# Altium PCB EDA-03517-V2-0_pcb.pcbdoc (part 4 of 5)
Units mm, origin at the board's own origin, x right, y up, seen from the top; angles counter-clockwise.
Board outline 220 x 264 mm, 8 copper layers (Top Layer, L2, L3, L4, L5, L6, L7, Bottom Layer), stack 2.18 mm thick; 439 components, 290 nets, 1011 pads, 273 vias.
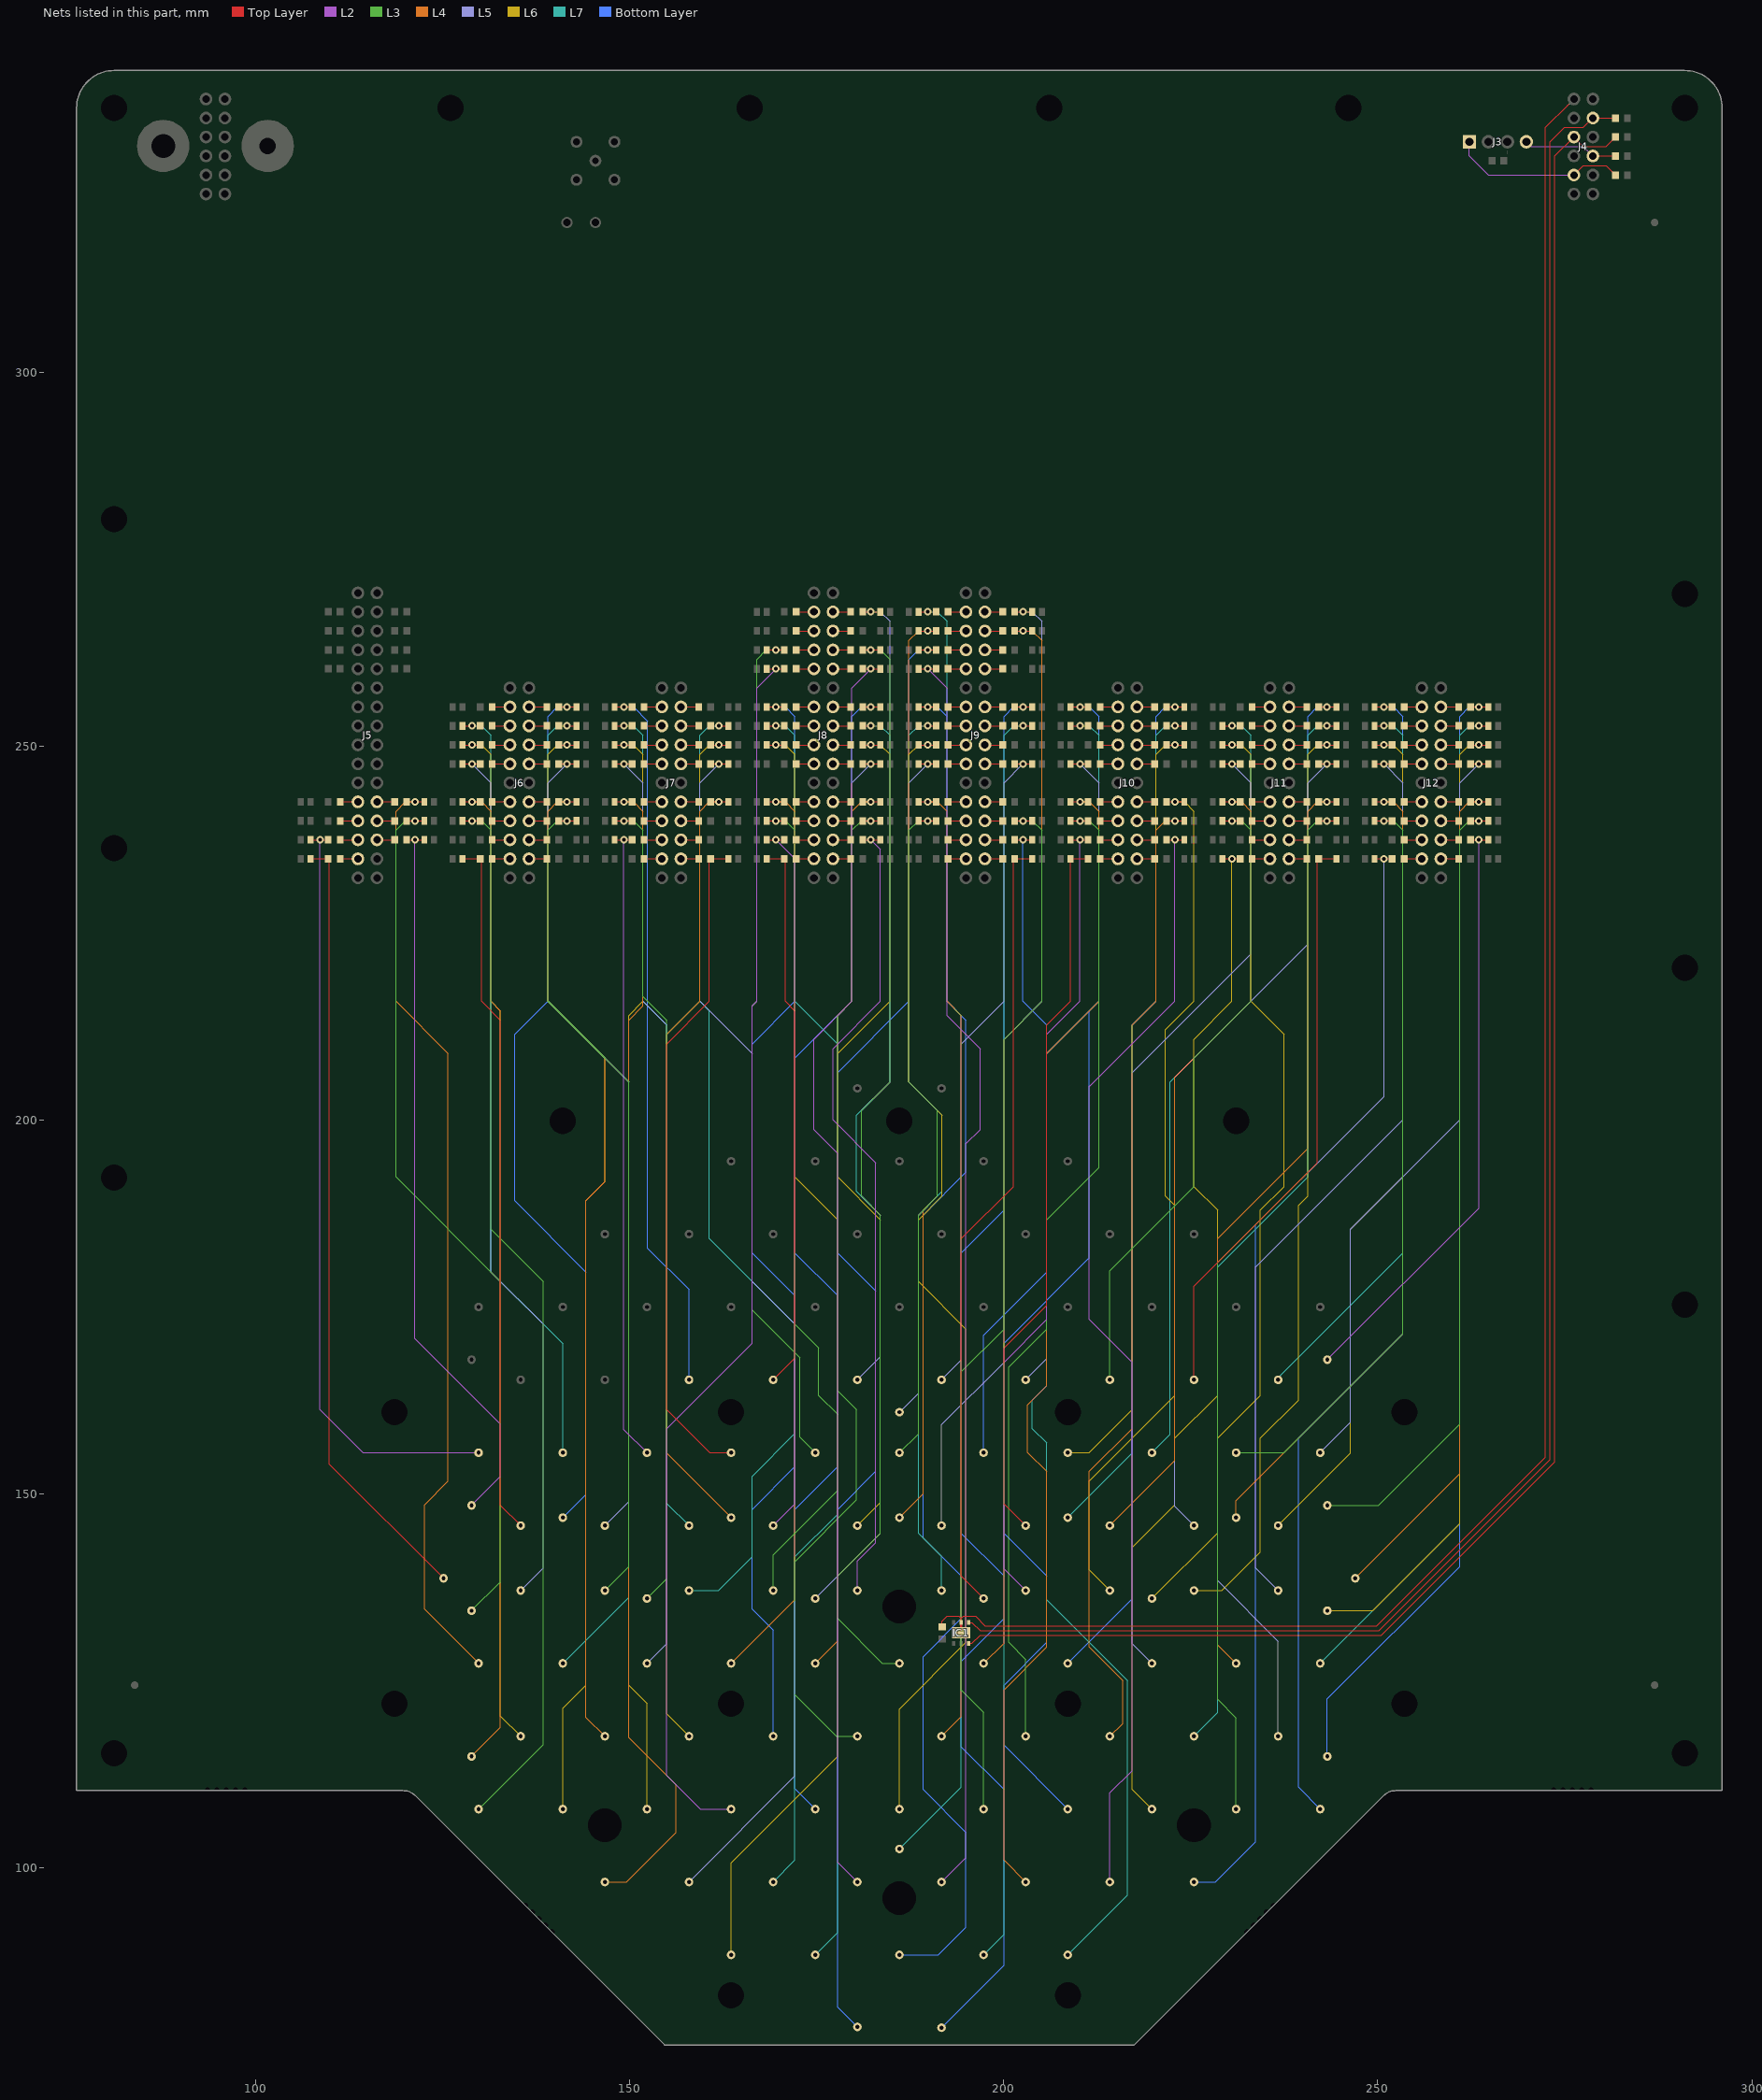
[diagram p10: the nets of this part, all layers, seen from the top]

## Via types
v1: diameter 1, hole 0.5, Top Layer to Bottom Layer, tented both sides, 273 vias

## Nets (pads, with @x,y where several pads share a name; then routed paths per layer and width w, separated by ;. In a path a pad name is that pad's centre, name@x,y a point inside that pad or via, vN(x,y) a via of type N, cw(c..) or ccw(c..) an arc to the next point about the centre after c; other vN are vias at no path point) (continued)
NetPP30_1: PP30.1 RB19.1 RS19.1 | length 96.7
  Top Layer w0.152: RB19.1@147.97,255.27 v1(149.225,255.27) RS19.1@150.33,255.27
  Bottom Layer w0.152: v1(149.225,255.27) 150.495,255.27 152.4,253.365 152.4,182.88 157.925,177.355 PP30.1@157.925,165.283
NetPP31_1: PP31.1 RB124.1 RS124.1 | length 73.8
  Top Layer w0.152: RB124.1@168.29,234.95 RS124.1@170.65,234.95 170.815,234.785 170.815,215.9 172.085,214.63 172.085,168.191 PP31.1@169.177,165.283
NetPP32_1: PP32.1 RB2.1 RS2.1 | length 110.8
  Top Layer w0.152: RS2.1@181.14,267.97 RB2.1@183.5,267.97
  L5 w0.152: PP32.1@180.429,165.283 183.515,168.369 183.515,187.325 180.975,189.865 180.975,201.295 184.785,205.105 184.785,266.7 183.515,267.97 v1(182.245,267.97)
NetPP33_1: PP33.1 RB65.1 RS65.1 | length 89.2
  Top Layer w0.152: RS65.1@201.46,247.65 RB65.1@203.82,247.65
  L5 w0.152: PP33.1@191.681,165.283 194.31,167.912 194.31,210.185 200.025,215.9 200.025,245.11 v1(202.565,247.65)
NetPP34_1: PP34.1 RB67.1 RS67.1 | length 89.8
  Top Layer w0.152: RB67.1@208.93,247.65 v1(210.185,247.65) RS67.1@211.29,247.65
  L5 w0.152: PP34.1@202.933,165.283 205.74,168.09 205.74,208.915 212.725,215.9 212.725,245.11 v1(210.185,247.65)
NetPP35_1: PP35.1 RB101.1 RS101.1 | length 86.7
  Top Layer w0.152: RB101.1@229.25,240.03 v1(230.505,240.03) RS101.1@231.61,240.03
  L3 w0.152: PP35.1@214.185,165.283 214.185,179.895 225.425,191.135 225.425,208.28 233.045,215.9 233.045,238.76 231.775,240.03 v1(230.505,240.03)
NetPP36_1: PP36.1 RB133.1 RS133.1 | length 78.9
  Top Layer w0.152: PP36.1@225.437,165.283 225.437,177.812 241.935,194.31 241.935,234.785 RS133.1@242.1,234.95 RB133.1@244.475,234.95
NetPP37_1: PP37.1 RB43.1 RS43.1 | length 98.5
  Top Layer w0.152: RB43.1@249.57,252.73 v1(250.825,252.73) RS43.1@251.93,252.73
  L7 w0.152: PP37.1@236.689,165.283 236.689,165.569 253.365,182.245 253.365,222.885 253.365,251.46 252.095,252.73 v1(250.825,252.73)
NetPP38_1: PP38.1 RB120.1 RS120.1 | length 80.3
  Top Layer w0.152: RS120.1@262.42,237.49 v1(263.525,237.49) RB120.1@264.78,237.49
  L2 w0.152: PP38.1@243.258,167.986 263.525,188.253 v1(263.525,237.49)
NetPP39_1: PP39.1 RB66.1 RS66.1 | length 93.8
  Top Layer w0.152: RB66.1@188.61,247.65 v1(189.865,247.65) RS66.1@190.97,247.65
  L5 w0.152: PP39.1@186.055,160.96 188.595,163.5 188.595,187.325 191.135,189.865 191.135,201.295 187.325,205.105 187.325,245.11 v1(189.865,247.65)
NetPP40_1: PP40.1 RB105.1 RS105.1 | length 102.2
  Top Layer w0.152: RB105.1@107.33,237.49 v1(108.585,237.49) RS105.1@109.69,237.49
  L2 w0.152: v1(108.585,237.49) 108.585,161.29 114.337,155.538 PP40.1@129.795,155.538
NetPP41_1: PP41.1 RB31.1 RS31.1 | length 105.3
  Top Layer w0.152: RB31.1@127.65,252.73 v1(128.905,252.73) RS31.1@130.01,252.73
  L7 w0.152: v1(128.905,252.73) 130.175,252.73 131.445,251.46 131.445,179.705 141.047,170.103 PP41.1@141.047,155.538
NetPP42_1: PP42.1 RB108.1 RS108.1 | length 85.6
  Top Layer w0.152: RB108.1@147.97,237.49 RS108.1@150.33,237.49
  L2 w0.152: v1(149.225,237.49) 149.225,158.612 PP42.1@152.299,155.538
NetPP43_1: PP43.1 RB128.1 RS128.1 | length 89.4
  Top Layer w0.152: RB128.1@163.18,234.95 RS128.1@160.82,234.95 160.655,234.785 160.655,215.9 154.94,210.185 154.94,161.29 160.692,155.538 PP43.1@163.551,155.538
NetPP44_1: PP44.1 RB9.1 RS9.1 | length 115.3
  Top Layer w0.152: RB9.1@168.29,262.89 v1(169.545,262.89) RS9.1@170.65,262.89
  L3 w0.152: v1(169.545,262.89) 168.275,262.89 167.005,261.62 167.005,215.9 166.37,215.265 166.37,174.625 172.72,168.275 172.72,157.621 PP44.1@174.803,155.538
NetPP45_1: PP45.1 RB98.1 RS98.1 | length 92.3
  Top Layer w0.152: RB98.1@188.61,240.03 v1(189.865,240.03) RS98.1@190.97,240.03
  L3 w0.152: PP45.1@186.055,155.538 188.595,158.078 188.595,187.325 191.135,189.865 191.135,201.295 187.325,205.105 187.325,238.76 188.595,240.03 v1(189.865,240.03)
NetPP46_1: PP46.1 RB111.1 RS111.1 | length 89.1
  Top Layer w0.152: RS111.1@201.46,237.49 v1(202.565,237.49) RB111.1@203.82,237.49
  Bottom Layer w0.152: PP46.1@197.307,155.538 197.307,171.272 205.74,179.705 205.74,212.725 202.565,215.9 v1(202.565,237.49)
NetPP47_1: PP47.1 RB54.1 RS54.1 | length 105.4
  Top Layer w0.152: RS54.1@221.78,250.19 v1(222.885,250.19) RB54.1@224.14,250.19
  L6 w0.152: PP47.1@208.559,155.538 211.418,155.538 217.17,161.29 217.17,212.725 220.345,215.9 220.345,248.92 221.615,250.19 v1(222.885,250.19)
NetPP48_1: PP48.1 RB41.1 RS41.1 | length 106.8
  Top Layer w0.152: RB41.1@229.25,252.73 v1(230.505,252.73) RS41.1@231.61,252.73
  L7 w0.152: PP48.1@219.811,155.538 222.25,157.977 222.25,205.105 233.045,215.9 233.045,251.46 231.775,252.73 v1(230.505,252.73)
NetPP49_1: PP49.1 RB103.1 RS103.1 | length 101.6
  Top Layer w0.152: RB103.1@249.57,240.03 v1(250.825,240.03) RS103.1@251.93,240.03
  L3 w0.152: PP49.1@231.063,155.538 237.453,155.538 253.365,171.45 253.365,238.76 252.095,240.03 v1(250.825,240.03)
NetPP50_1: PP50.1 RB72.1 RS72.1 | length 103.3
  Top Layer w0.152: RS72.1@262.42,247.65 v1(263.525,247.65) RB72.1@264.78,247.65
  L5 w0.152: PP50.1@242.315,155.538 246.38,159.603 246.38,185.42 260.985,200.025 260.985,245.11 v1(263.525,247.65)
NetPP51_1: PP51.1 RB106.1 RS106.1 | length 97.7
  Top Layer w0.152: RS106.1@120.18,237.49 v1(121.285,237.49) RB106.1@122.54,237.49
  L2 w0.152: v1(121.285,237.49) 121.285,170.815 132.715,159.385 132.715,152.36 PP51.1@128.852,148.497
NetPP52_1: PP52.1 RB127.1 RS127.1 | length 93.8
  Top Layer w0.152: RB127.1@127.65,234.95 RS127.1@130.01,234.95 130.175,234.785 130.175,215.9 132.715,213.36 132.715,148.5 PP52.1@135.421,145.794
NetPP53_1: PP53.1 RB60.1 RS60.1 | length 111.1
  Top Layer w0.152: RS60.1@140.5,247.65 v1(141.605,247.65) RB60.1@142.86,247.65
  L5 w0.152: v1(141.605,247.65) 139.065,245.11 139.065,215.9 149.86,205.105 149.86,148.981 PP53.1@146.673,145.794
NetPP54_1: PP54.1 RB33.1 RS33.1 | length 113.6
  Top Layer w0.152: RB33.1@147.97,252.73 v1(149.225,252.73) RS33.1@150.33,252.73
  L7 w0.152: v1(149.225,252.73) 150.495,252.73 151.765,251.46 151.765,215.9 154.94,212.725 154.94,148.779 PP54.1@157.925,145.794
NetPP55_1: PP55.1 RB109.1 RS109.1 | length 96.3
  Top Layer w0.152: RB109.1@168.29,237.49 v1(169.545,237.49) RS109.1@170.65,237.49
  L2 w0.152: PP55.1@169.177,145.794 172.085,148.702 172.085,234.95 v1(169.545,237.49)
NetPP56_1: PP56.1 RB50.1 RS50.1 | length 115.1
  Top Layer w0.152: RS50.1@181.14,250.19 RB50.1@183.5,250.19
  L6 w0.152: PP56.1@180.429,145.794 183.515,148.88 183.515,186.69 177.8,192.405 177.8,208.915 184.785,215.9 184.785,248.92 183.515,250.19 v1(182.245,250.19)
NetPP57_1: PP57.1 RB3.1 RS4.1 | length 131.9
  Top Layer w0.152: RS4.1@201.46,267.97 RB3.1@203.82,267.97
  L5 w0.152: PP57.1@191.681,145.794 191.681,159.296 200.025,167.64 200.025,210.82 205.105,215.9 205.105,225.425 205.105,266.7 203.835,267.97 v1(202.565,267.97)
NetPP58_1: PP58.1 RB130.1 RS130.1 | length 96.4
  Top Layer w0.152: PP58.1@202.933,145.794 200.025,148.702 200.025,169.545 205.74,175.26 205.74,212.725 208.915,215.9 208.915,234.935 RB130.1@208.93,234.95 RS130.1@211.29,234.95
NetPP59_1: PP59.1 RB85.1 RS85.1 | length 108.7
  Top Layer w0.152: RB85.1@229.25,242.57 RS85.1@231.61,242.57
  L4 w0.152: PP59.1@214.185,145.794 222.885,154.494 222.885,205.74 233.045,215.9 233.045,241.3 231.775,242.57 v1(230.505,242.57)
NetPP60_1: PP60.1 RB70.1 RS70.1 | length 113.7
  Top Layer w0.152: RS70.1@242.1,247.65 v1(243.205,247.65) RB70.1@244.46,247.65
  L5 w0.152: PP60.1@225.437,145.794 222.885,148.346 222.885,205.74 240.665,223.52 240.665,245.11 v1(243.205,247.65)
NetPP61_1: PP61.1 RB57.1 RS57.1 | length 115.5
  Top Layer w0.152: RB57.1@249.57,250.19 v1(250.825,250.19) RS57.1@251.93,250.19
  L6 w0.152: PP61.1@236.689,145.794 246.38,155.485 246.38,185.42 253.365,192.405 253.365,248.92 252.095,250.19 v1(250.825,250.19)
NetPP62_1: PP62.1 RB104.1 RS104.1 | length 107
  Top Layer w0.152: RS104.1@262.42,240.03 v1(263.525,240.03) RB104.1@264.78,240.03
  L3 w0.152: PP62.1@243.258,148.497 250.097,148.497 260.985,159.385 260.985,238.76 262.255,240.03 v1(263.525,240.03)
NetPP63_1: PP63.1 RB121.1 RS121.1 | length 104.9
  Top Layer w0.152: RB121.1@107.33,234.95 RS121.1@109.69,234.95 109.855,234.785 109.855,154.01 PP63.1@125.112,138.753
NetPP64_1: PP64.1 RB18.1 RS18.1 | length 119.6
  Top Layer w0.152: RS18.1@140.5,255.27 RB18.1@142.86,255.27
  Bottom Layer w0.152: PP64.1@141.047,146.864 144.145,149.962 144.145,179.705 134.62,189.23 134.62,211.455 139.065,215.9 139.065,254 140.335,255.27 v1(141.605,255.27)
NetPP65_1: PP65.1 RB92.1 RS92.1 | length 110.5
  Top Layer w0.152: RB92.1@147.97,240.03 RS92.1@150.33,240.03
  L3 w0.152: v1(149.225,240.03) 150.495,240.03 151.765,238.76 151.765,216.535 154.94,213.36 154.94,138.69 PP65.1@152.299,136.049
NetPP66_1: PP66.1 RB81.1 RS81.1 | length 105.3
  Top Layer w0.152: RS81.1@160.82,242.57 RB81.1@163.18,242.57
  L4 w0.152: v1(161.925,242.57) 160.655,242.57 159.385,241.3 159.385,221.297 159.385,215.9 154.94,211.455 154.94,155.475 PP66.1@163.551,146.864
NetPP67_1: PP67.1 RB64.1 RS64.1 | length 117
  Top Layer w0.152: RS64.1@181.14,247.65 RB64.1@183.5,247.65
  L5 w0.152: PP67.1@174.803,136.049 177.8,139.046 177.8,213.995 179.705,215.9 179.705,245.11 v1(182.245,247.65)
NetPP68_1: PP68.1 RB8.1 RS7.1 | length 126.4
  Top Layer w0.152: RB8.1@188.61,265.43 v1(189.865,265.43) RS7.1@190.97,265.43
  L4 w0.152: PP68.1@186.055,146.864 189.23,150.039 189.23,187.96 191.135,189.865 191.135,201.295 187.325,205.105 187.325,264.16 188.595,265.43 v1(189.865,265.43)
NetPP69_1: PP69.1 RB126.1 RS126.1 | length 105.5
  Top Layer w0.152: PP69.1@197.307,136.049 194.31,139.046 194.31,184.15 201.295,191.135 201.295,234.785 RS126.1@201.46,234.95 RB126.1@203.82,234.95
NetPP70_1: PP70.1 RB40.1 RS40.1 | length 114.9
  Top Layer w0.152: RS40.1@221.78,252.73 RB40.1@224.14,252.73
  L7 w0.152: PP70.1@208.559,146.864 217.17,155.475 217.17,212.725 220.345,215.9 220.345,251.46 221.615,252.73 v1(222.885,252.73)
NetPP71_1: PP71.1 RB55.1 RS55.1 | length 127.5
  Top Layer w0.152: RB55.1@229.25,250.19 v1(230.505,250.19) RS55.1@231.61,250.19
  L6 w0.152: PP71.1@219.811,136.049 228.6,144.838 228.6,157.48 234.315,163.195 234.315,187.96 237.49,191.135 237.49,211.455 233.045,215.9 233.045,248.92 231.775,250.19 v1(230.505,250.19)
NetPP72_1: PP72.1 RB87.1 RS87.1 | length 109.1
  Top Layer w0.152: RB87.1@249.57,242.57 v1(250.825,242.57) RS87.1@251.93,242.57
  L4 w0.152: PP72.1@231.063,146.864 231.063,149.148 253.365,171.45 253.365,241.3 252.095,242.57 v1(250.825,242.57)
NetPP73_1: PP73.1 RB88.1 RS88.1 | length 113.8
  Top Layer w0.152: RS88.1@262.42,242.57 v1(263.525,242.57) RB88.1@264.78,242.57
  L4 w0.152: PP73.1@246.998,138.753 260.985,152.74 260.985,241.3 262.255,242.57 v1(263.525,242.57)
NetPP74_1: PP74.1 RB90.1 RS90.1 | length 117.2
  Top Layer w0.152: RS90.1@120.18,240.03 v1(121.285,240.03) RB90.1@122.54,240.03
  L3 w0.152: v1(121.285,240.03) 120.015,240.03 118.745,238.76 118.745,192.405 132.715,178.435 132.715,138.279 PP74.1@128.852,134.415
NetPP75_1: PP75.1 RB59.1 RS59.1 | length 118.1
  Top Layer w0.152: RB59.1@127.65,247.65 v1(128.905,247.65) RS59.1@130.01,247.65
  L5 w0.152: v1(128.905,247.65) 131.445,245.11 131.445,179.705 138.43,172.72 138.43,140.128 PP75.1@135.421,137.119
NetPP76_1: PP76.1 RB91.1 RS91.1 | length 112.9
  Top Layer w0.152: RS91.1@140.5,240.03 RB91.1@142.86,240.03
  L3 w0.152: v1(141.605,240.03) 140.335,240.03 139.065,238.76 139.065,215.9 149.86,205.105 149.86,140.306 PP76.1@146.673,137.119
NetPP77_1: PP77.1 RB34.1 RS34.1 | length 133.2
  Top Layer w0.152: RS34.1@160.82,252.73 v1(161.925,252.73) RB34.1@163.18,252.73
  L7 w0.152: PP77.1@157.925,137.119 161.884,137.119 166.37,141.605 166.37,152.4 172.085,158.115 172.085,172.72 160.655,184.15 160.655,214.63 159.385,215.9 159.385,251.46 160.655,252.73 v1(161.925,252.73)
NetPP78_1: PP78.1 RB93.1 RS93.1 | length 113
  Top Layer w0.152: RB93.1@168.29,240.03 v1(169.545,240.03) RS93.1@170.65,240.03
  L3 w0.152: PP78.1@169.177,137.119 169.177,141.872 177.8,150.495 177.8,160.655 175.26,163.195 175.26,169.545 172.085,172.72 172.085,238.76 170.815,240.03 v1(169.545,240.03)
NetPP79_1: PP79.1 RB110.1 RS110.1 | length 109.3
  Top Layer w0.152: RS110.1@181.14,237.49 v1(182.245,237.49) RB110.1@183.5,237.49
  L2 w0.152: PP79.1@180.429,137.119 180.429,141.059 182.88,143.51 182.88,194.31 177.165,200.025 177.165,209.55 183.515,215.9 183.515,236.22 v1(182.245,237.49)
NetPP80_1: PP80.1 RB38.1 RS38.1 | length 124.2
  Top Layer w0.152: RB38.1@188.61,252.73 v1(189.865,252.73) RS38.1@190.97,252.73
  L7 w0.152: v1(189.865,252.73) 188.595,252.73 187.325,251.46 187.325,205.105 191.77,200.66 191.77,190.5 188.595,187.325 188.595,144.78 191.681,141.694 PP80.1@191.681,137.119
NetPP81_1: PP81.1 RB115.1 RS115.1 | length 108.1
  Top Layer w0.152: RB115.1@208.93,237.49 v1(210.185,237.49) RS115.1@211.29,237.49
  L2 w0.152: PP81.1@202.933,137.119 200.025,140.027 200.025,167.64 205.74,173.355 205.74,211.455 210.185,215.9 v1(210.185,237.49)
NetPP82_1: PP82.1 RB84.1 RS84.1 | length 117.6
  Top Layer w0.152: RS84.1@221.78,242.57 v1(222.885,242.57) RB84.1@224.14,242.57
  L6 w0.152: PP82.1@214.185,137.119 211.455,139.849 211.455,151.765 222.885,163.195 222.885,188.595 221.615,189.865 221.615,212.09 225.425,215.9 225.425,241.3 224.155,242.57 v1(222.885,242.57)
NetPP83_1: PP83.1 RB56.1 RS56.1 | length 125.7
  Top Layer w0.152: RS56.1@242.1,250.19 v1(243.205,250.19) RB56.1@244.46,250.19
  L6 w0.152: PP83.1@225.437,137.119 229.194,137.119 234.315,142.24 234.315,157.48 239.395,162.56 239.395,188.595 240.665,189.865 240.665,248.92 241.935,250.19 v1(243.205,250.19)
NetPP84_1: PP84.1 RB71.1 RS71.1 | length 123.3
  Top Layer w0.152: RB71.1@249.57,247.65 v1(250.825,247.65) RS71.1@251.93,247.65
  L5 w0.152: PP84.1@236.689,137.119 233.68,140.128 233.68,180.34 253.365,200.025 253.365,245.11 v1(250.825,247.65)
NetPP85_1: PP85.1 RB58.1 RS58.1 | length 130.8
  Top Layer w0.152: RS58.1@262.42,250.19 v1(263.525,250.19) RB58.1@264.78,250.19
  L6 w0.152: PP85.1@243.258,134.415 249.35,134.415 260.985,146.05 260.985,248.92 262.255,250.19 v1(263.525,250.19)
NetPP86_1: PP86.1 RB74.1 RS74.1 | length 126.6
  Top Layer w0.152: RS74.1@120.18,242.57 v1(121.285,242.57) RB74.1@122.54,242.57
  L4 w0.152: v1(121.285,242.57) 120.015,242.57 118.745,241.3 118.745,215.9 125.73,208.915 125.73,151.765 122.555,148.59 122.555,134.615 PP86.1@129.795,127.375
NetPP87_1: PP87.1 RB32.1 RS32.1 | length 137.6
  Top Layer w0.152: RS32.1@140.5,252.73 v1(141.605,252.73) RB32.1@142.86,252.73
  L7 w0.152: PP87.1@141.047,127.375 149.86,136.188 149.86,205.105 139.065,215.9 139.065,251.46 140.335,252.73 v1(141.605,252.73)
NetPP88_1: PP88.1 RB61.1 RS61.1 | length 126.1
  Top Layer w0.152: RB61.1@147.97,247.65 v1(149.225,247.65) RS61.1@150.33,247.65
  L5 w0.152: v1(149.225,247.65) 151.765,245.11 151.765,215.9 154.94,212.725 154.94,130.016 PP88.1@152.299,127.375
NetPP89_1: PP89.1 RB77.1 RS77.1 | length 122.9
  Top Layer w0.152: RB77.1@168.29,242.57 v1(169.545,242.57) RS77.1@170.65,242.57
  L4 w0.152: PP89.1@163.551,127.375 172.085,135.909 172.085,241.3 170.815,242.57 v1(169.545,242.57)
NetPP90_1: PP90.1 RB78.1 RS78.1 | length 121.4
  Top Layer w0.152: RS78.1@181.14,242.57 v1(182.245,242.57) RB78.1@183.5,242.57
  L4 w0.152: PP90.1@174.803,127.375 177.8,130.372 177.8,213.995 179.705,215.9 179.705,241.3 180.975,242.57 v1(182.245,242.57)
NetPP91_1: PP91.1 RB10.1 RS10.1 | length 149.4
  Top Layer w0.152: RS10.1@181.14,262.89 v1(182.245,262.89) RB10.1@183.5,262.89
  L3 w0.152: v1(182.245,262.89) 183.515,262.89 184.785,261.62 184.785,205.105 180.975,201.295 180.975,189.865 183.515,187.325 183.515,144.78 177.8,139.065 177.8,133.35 183.775,127.375 PP91.1@186.055,127.375
NetPP92_1: PP92.1 RB7.1 RS8.1 | length 145.4
  Top Layer w0.152: RS8.1@201.46,265.43 v1(202.565,265.43) RB7.1@203.82,265.43
  L4 w0.152: PP92.1@197.307,127.375 200.025,130.093 200.025,210.82 205.105,215.9 205.105,264.16 203.835,265.43 v1(202.565,265.43)
NetPP93_1: PP93.1 RB26.1 RS26.1 | length 136.9
  Top Layer w0.152: RS26.1@221.78,255.27 RB26.1@224.14,255.27
  Bottom Layer w0.152: PP93.1@208.559,127.375 217.17,135.986 217.17,212.725 220.345,215.9 220.345,254 221.615,255.27 v1(222.885,255.27)
NetPP94_1: PP94.1 RB69.1 RS69.1 | length 131.4
  Top Layer w0.152: RB69.1@229.25,247.65 v1(230.505,247.65) RS69.1@231.61,247.65
  L5 w0.152: PP94.1@219.811,127.375 217.17,130.016 217.17,206.375 233.045,222.25 233.045,245.11 v1(230.505,247.65)
NetPP95_1: PP95.1 RB86.1 RS86.1 | length 125.4
  Top Layer w0.152: RS86.1@242.1,242.57 v1(243.205,242.57) RB86.1@244.46,242.57
  L4 w0.152: PP95.1@231.063,127.375 228.6,129.838 228.6,184.15 240.665,196.215 240.665,241.3 241.935,242.57 v1(243.205,242.57)
NetPP96_1: PP96.1 RB44.1 RS44.1 | length 137.2
  Top Layer w0.152: RS44.1@262.42,252.73 v1(263.525,252.73) RB44.1@264.78,252.73
  L7 w0.152: PP96.1@242.315,127.375 260.985,146.045 260.985,251.46 262.255,252.73 v1(263.525,252.73)
NetPP97_1: PP97.1 RB80.1 RS80.1 | length 133.9
  Top Layer w0.152: RB80.1@127.65,242.57 RS80.1@130.01,242.57
  L4 w0.152: PP97.1@128.852,114.926 132.715,118.79 132.715,214.63 131.445,215.9 131.445,241.3 130.175,242.57 v1(128.905,242.57)
NetPP98_1: PP98.1 RB45.1 RS45.1 | length 138.4
  Top Layer w0.152: RB45.1@127.65,250.19 v1(128.905,250.19) RS45.1@130.01,250.19
  L6 w0.152: v1(128.905,250.19) 130.175,250.19 131.445,248.92 131.445,220.98 131.445,215.9 132.715,214.63 132.715,120.336 PP98.1@135.421,117.63
NetPP99_1: PP99.1 RB75.1 RS75.1 | length 134.4
  Top Layer w0.152: RS75.1@140.5,242.57 RB75.1@142.86,242.57
  L4 w0.152: v1(141.605,242.57) 140.335,242.57 139.065,241.3 139.065,215.9 146.685,208.28 146.685,191.77 144.145,189.23 144.145,120.158 PP99.1@146.673,117.63
NetPP100_1: PP100.1 RB48.1 RS48.1 | length 139.8
  Top Layer w0.152: RS48.1@160.82,250.19 v1(161.925,250.19) RB48.1@163.18,250.19
  L6 w0.152: PP100.1@157.925,117.63 154.94,120.615 154.94,211.455 159.385,215.9 159.385,248.92 160.655,250.19 v1(161.925,250.19)
NetPP101_1: PP101.1 RB21.1 RS21.1 | length 150.1
  Top Layer w0.152: RB21.1@168.29,255.27 RS21.1@170.65,255.27
  Bottom Layer w0.152: PP101.1@169.177,117.63 169.177,131.813 166.37,134.62 166.37,147.955 172.085,153.67 172.085,176.53 166.37,182.245 166.37,210.185 172.085,215.9 172.085,254 170.815,255.27 v1(169.545,255.27)
NetPP102_1: PP102.1 RB94.1 RS94.1 | length 136.9
  Top Layer w0.152: RS94.1@181.14,240.03 v1(182.245,240.03) RB94.1@183.5,240.03
  L3 w0.152: PP102.1@180.429,117.63 177.645,117.63 172.085,123.19 172.085,140.97 180.34,149.225 180.34,161.29 177.8,163.83 177.8,213.995 179.705,215.9 179.705,238.76 180.975,240.03 v1(182.245,240.03)
NetPP103_1: PP103.1 RB82.1 RS82.1 | length 131
  Top Layer w0.152: RB82.1@188.61,242.57 v1(189.865,242.57) RS82.1@190.97,242.57
  L4 w0.152: v1(189.865,242.57) 191.135,242.57 192.405,241.3 192.405,215.9 194.31,213.995 194.31,120.259 PP103.1@191.681,117.63
NetPP104_1: PP104.1 RB99.1 RS99.1 | length 132.5
  Top Layer w0.152: RB99.1@208.93,240.03 v1(210.185,240.03) RS99.1@211.29,240.03
  L3 w0.152: PP104.1@202.933,117.63 202.933,127.902 200.66,130.175 200.66,167.005 205.74,172.085 205.74,186.69 212.725,193.675 212.725,238.76 211.455,240.03 v1(210.185,240.03)
NetPP105_1: PP105.1 RB100.1 RS100.1 | length 132.8
  Top Layer w0.152: RS100.1@221.78,240.03 v1(222.885,240.03) RB100.1@224.14,240.03
  L4 w0.152: PP105.1@214.185,117.63 215.9,119.345 215.9,125.095 211.455,129.54 211.455,153.035 217.17,158.75 217.17,212.725 220.345,215.9 220.345,238.76 221.615,240.03 v1(222.885,240.03)
NetPP106_1: PP106.1 RB42.1 RS42.1 | length 145.6
  Top Layer w0.152: RS42.1@242.1,252.73 v1(243.205,252.73) RB42.1@244.46,252.73
  L7 w0.152: PP106.1@225.437,117.63 228.6,120.793 228.6,180.34 240.665,192.405 240.665,251.46 241.935,252.73 v1(243.205,252.73)
NetPP107_1: PP107.1 RB134.1 RS134.1 | length 132.2
  Top Layer w0.152: RB134.1@249.57,234.95 v1(250.825,234.95) RS134.1@251.93,234.95
  L5 w0.152: PP107.1@236.689,117.63 236.689,130.341 228.6,138.43 228.6,180.975 250.825,203.2 v1(250.825,234.95)
NetPP108_1: PP108.1 RB30.1 RS30.1 | length 151.8
  Top Layer w0.152: RS30.1@262.42,255.27 RB30.1@264.78,255.27
  Bottom Layer w0.152: PP108.1@243.258,114.926 243.258,122.608 260.985,140.335 260.985,254 262.255,255.27 v1(263.525,255.27)
NetPP109_1: PP109.1 RB96.1 RS96.1 | length 142.8
  Top Layer w0.152: RB96.1@127.65,240.03 v1(128.905,240.03) RS96.1@130.01,240.03
  L3 w0.152: v1(128.905,240.03) 130.175,240.03 131.445,238.76 131.445,185.42 138.43,178.435 138.43,116.521 PP109.1@129.795,107.886
NetPP110_1: PP110.1 RB46.1 RS46.1 | length 152
  Top Layer w0.152: RS46.1@140.5,250.19 v1(141.605,250.19) RB46.1@142.86,250.19
  L6 w0.152: PP110.1@141.047,107.886 141.047,121.362 144.145,124.46 144.145,189.23 146.685,191.77 146.685,208.28 139.065,215.9 139.065,219.71 139.065,248.92 140.335,250.19 v1(141.605,250.19)
NetPP111_1: PP111.1 RB47.1 RS47.1 | length 148.3
  Top Layer w0.152: RB47.1@147.97,250.19 v1(149.225,250.19) RS47.1@150.33,250.19
  L6 w0.152: v1(149.225,250.19) 150.495,250.19 151.765,248.92 151.765,215.9 149.86,213.995 149.86,124.46 152.299,122.021 PP111.1@152.299,107.886
NetPP112_1: PP112.1 RB13.1 RS13.1 | length 166.8
  Top Layer w0.152: RB13.1@168.29,260.35 v1(169.545,260.35) RS13.1@170.65,260.35
  L2 w0.152: PP112.1@163.551,107.886 159.449,107.886 154.94,112.395 154.94,158.75 166.37,170.18 166.37,215.265 167.005,215.9 167.005,257.81 v1(169.545,260.35)
NetPP113_1: PP113.1 RB22.1 RS22.1 | length 160.6
  Top Layer w0.152: RS22.1@181.14,255.27 RB22.1@183.5,255.27
  Bottom Layer w0.152: PP113.1@174.803,107.886 172.085,110.604 172.085,147.955 177.8,153.67 177.8,176.53 172.085,182.245 172.085,208.28 179.705,215.9 179.705,254 180.975,255.27 v1(182.245,255.27)
NetPP114_1: PP114.1 RB52.1 RS52.1 | length 155.9
  Top Layer w0.152: RB52.1@188.61,250.19 v1(189.865,250.19) RS52.1@190.97,250.19
  L6 w0.152: PP114.1@186.055,107.886 186.055,121.285 194.945,130.175 194.945,172.085 188.595,178.435 188.595,186.69 191.77,189.865 191.77,200.66 187.325,205.105 187.325,248.92 188.595,250.19 v1(189.865,250.19)
NetPP115_1: PP115.1 RB95.1 RS95.1 | length 142
  Top Layer w0.152: RS95.1@201.46,240.03 v1(202.565,240.03) RB95.1@203.82,240.03
  L3 w0.152: PP115.1@197.307,107.886 197.307,120.828 194.31,123.825 194.31,166.37 200.025,172.085 200.025,210.82 205.105,215.9 205.105,238.76 203.835,240.03 v1(202.565,240.03)
NetPP116_1: PP116.1 RB25.1 RS25.1 | length 165.1
  Top Layer w0.152: RB25.1@208.93,255.27 v1(210.185,255.27) RS25.1@211.29,255.27
  Bottom Layer w0.152: PP116.1@208.559,107.886 200.025,116.42 200.025,124.46 205.74,130.175 205.74,139.065 200.025,144.78 200.025,170.18 211.455,181.61 211.455,214.63 212.725,215.9 212.725,254 211.455,255.27 v1(210.185,255.27)
NetPP117_1: PP117.1 RB132.1 RS132.1 | length 138.7
  Top Layer w0.152: RB132.1@229.25,234.95 v1(230.505,234.95) RS132.1@231.61,234.95
  L6 w0.152: PP117.1@219.811,107.886 217.17,110.527 217.17,142.875 222.885,148.59 222.885,157.48 228.6,163.195 228.6,187.96 225.425,191.135 225.425,210.82 230.505,215.9 v1(230.505,234.95)
NetPP118_1: PP118.1 RB102.1 RS102.1 | length 142.3
  Top Layer w0.152: RS102.1@242.1,240.03 RB102.1@244.46,240.03
  L3 w0.152: PP118.1@231.063,107.886 231.063,120.092 228.6,122.555 228.6,180.975 240.665,193.04 240.665,238.76 241.935,240.03 v1(243.205,240.03)
NetPP119_1: PP119.1 RB29.1 RS29.1 | length 158.5
  Top Layer w0.152: RB29.1@249.57,255.27 v1(250.825,255.27) RS29.1@251.93,255.27
  Bottom Layer w0.152: PP119.1@242.315,107.886 239.395,110.806 239.395,157.48 253.365,171.45 253.365,223.52 253.365,254 252.095,255.27 v1(250.825,255.27)
NetPP120_1: PP120.1 RB4.1 RS3.1 | length 173.8
  Top Layer w0.152: RB4.1@188.61,267.97 v1(189.865,267.97) RS3.1@190.97,267.97
  L7 w0.152: PP120.1@186.055,102.56 194.31,110.815 194.31,213.995 192.405,215.9 192.405,266.7 191.135,267.97 v1(189.865,267.97)
NetPP121_1: PP121.1 RB76.1 RS76.1 | length 157.7
  Top Layer w0.152: RB76.1@147.97,242.57 RS76.1@150.33,242.57
  L4 w0.152: PP121.1@146.673,98.141 149.576,98.141 156.21,104.775 156.21,111.125 149.86,117.475 149.86,213.36 151.765,215.265 151.765,241.3 150.495,242.57 v1(149.225,242.57)
NetPP122_1: PP122.1 RB62.1 RS62.1 | length 164
  Top Layer w0.152: RS62.1@160.82,247.65 v1(161.925,247.65) RB62.1@163.18,247.65
  L5 w0.152: PP122.1@157.925,98.141 172.085,112.301 172.085,172.72 166.37,178.435 166.37,208.915 159.385,215.9 159.385,245.11 v1(161.925,247.65)
NetPP123_1: PP123.1 RB35.1 RS35.1 | length 164.7
  Top Layer w0.152: RB35.1@168.29,252.73 RS35.1@170.65,252.73
  L7 w0.152: PP123.1@169.177,98.141 172.085,101.049 172.085,141.605 177.8,147.32 177.8,210.185 172.085,215.9 172.085,251.46 170.815,252.73 v1(169.545,252.73)
NetPP124_1: PP124.1 RB14.1 RS14.1 | length 170.1
  Top Layer w0.152: RS14.1@181.14,260.35 v1(182.245,260.35) RB14.1@183.5,260.35
  L2 w0.152: PP124.1@180.429,98.141 177.8,100.77 177.8,195.58 174.625,198.755 174.625,210.82 179.705,215.9 179.705,257.81 v1(182.245,260.35)
NetPP125_1: PP125.1 RB16.1 RS15.1 | length 169.6
  Top Layer w0.152: RB16.1@188.61,260.35 v1(189.865,260.35) RS15.1@190.97,260.35
  L2 w0.152: v1(189.865,260.35) 192.405,257.81 192.405,213.995 196.85,209.55 196.85,198.755 194.945,196.85 194.945,101.405 PP125.1@191.681,98.141
NetPP126_1: PP126.1 RB83.1 RS83.1 | length 157.2
  Top Layer w0.152: RB83.1@208.93,242.57 v1(210.185,242.57) RS83.1@211.29,242.57
  L4 w0.152: PP126.1@202.933,98.141 200.025,101.049 200.025,123.825 205.74,129.54 205.74,153.035 203.2,155.575 203.2,161.925 205.74,164.465 205.74,208.915 212.725,215.9 212.725,241.3 211.455,242.57 v1(210.185,242.57)
NetPP127_1: PP127.1 RB116.1 RS116.1 | length 150
  Top Layer w0.152: RS116.1@221.78,237.49 v1(222.885,237.49) RB116.1@224.14,237.49
  L2 w0.152: PP127.1@214.185,98.141 214.185,110.045 217.17,113.03 217.17,167.64 211.455,173.355 211.455,204.47 222.885,215.9 v1(222.885,237.49)
NetPP128_1: PP128.1 RB28.1 RS28.1 | length 169.3
  Top Layer w0.152: RS28.1@242.1,255.27 RB28.1@244.46,255.27
  Bottom Layer w0.152: PP128.1@225.437,98.141 228.316,98.141 233.68,103.505 233.68,186.055 240.665,193.04 240.665,254 241.935,255.27 v1(243.205,255.27)
NetPP129_1: PP129.1 RB49.1 RS49.1 | length 174.2
  Top Layer w0.152: RB49.1@168.29,250.19 RS49.1@170.65,250.19
  L6 w0.152: PP129.1@163.551,88.397 163.551,100.686 177.8,114.935 177.8,186.69 172.085,192.405 172.085,248.92 170.815,250.19 v1(169.545,250.19)
NetPP130_1: PP130.1 RB36.1 RS36.1 | length 175.3
  Top Layer w0.152: RS36.1@181.14,252.73 RB36.1@183.5,252.73
  L7 w0.152: PP130.1@174.803,88.397 177.8,91.394 177.8,139.065 183.515,144.78 183.515,187.325 180.34,190.5 180.34,200.66 184.785,205.105 184.785,251.46 183.515,252.73 v1(182.245,252.73)
NetPP131_1: PP131.1 RB24.1 RS24.1 | length 187.8
  Top Layer w0.152: RB24.1@188.61,255.27 v1(189.865,255.27) RS24.1@190.97,255.27
  Bottom Layer w0.152: PP131.1@186.055,88.397 191.267,88.397 194.945,92.075 194.945,104.775 189.23,110.49 189.23,128.27 194.31,133.35 194.31,139.065 189.23,144.145 189.23,187.325 194.945,193.04 194.945,213.36 192.405,215.9 192.405,254 191.135,255.27 v1(189.865,255.27)
NetPP132_1: PP132.1 RB37.1 RS37.1 | length 169.6
  Top Layer w0.152: RS37.1@201.46,252.73 RB37.1@203.82,252.73
  L7 w0.152: PP132.1@197.307,88.397 200.025,91.115 200.025,251.46 201.295,252.73 v1(202.565,252.73)
NetPP133_1: PP133.1 RB39.1 RS39.1 | length 180.7
  Top Layer w0.152: RB39.1@208.93,252.73 v1(210.185,252.73) RS39.1@211.29,252.73
  L7 w0.152: PP133.1@208.559,88.397 216.535,96.373 216.535,125.095 205.74,135.89 205.74,156.845 203.835,158.75 203.835,162.56 205.74,164.465 205.74,208.915 212.725,215.9 212.725,251.46 211.455,252.73 v1(210.185,252.73)
NetPP134_1: PP134.1 RB12.1 RS11.1 | length 197.5
  Top Layer w0.152: RB12.1@188.61,262.89 v1(189.865,262.89) RS11.1@190.97,262.89
  Bottom Layer w0.152: PP134.1@180.435,78.76 177.8,81.395 177.8,147.955 182.88,153.035 182.88,177.165 177.8,182.245 177.8,206.375 187.325,215.9 187.325,261.62 188.595,262.89 v1(189.865,262.89)
NetPP135_1: PP135.1 RB23.1 RS23.1 | length 193.7
  Top Layer w0.152: RS23.1@201.46,255.27 RB23.1@203.82,255.27
  Bottom Layer w0.152: PP135.1@191.681,78.652 200.025,86.996 200.025,110.49 194.31,116.205 194.31,127.635 200.025,133.35 200.025,139.065 194.31,144.78 194.31,182.245 200.025,187.96 200.025,254 201.295,255.27 v1(202.565,255.27)
PP1: J8.3 RS125.2 | length 2.4
  Top Layer w0.152: J8.3@177.165,234.95 RS125.2@179.54,234.95
PP2: J9.15 RS51.2 | length 2.4
  Top Layer w0.152: J9.15@197.485,250.19 RS51.2@199.86,250.19
PP3: J7.7 RS97.2 | length 2.4
  Top Layer w0.152: J7.7@156.845,240.03 RS97.2@159.22,240.03
PP4: J8.30 RS1.2 | length 2.4
  Top Layer w0.152: RS1.2@172.25,267.97 J8.30@174.625,267.97
PP5: J9.6 RS114.2 | length 2.4
  Top Layer w0.152: RS114.2@192.57,237.49 J9.6@194.945,237.49
PP6: J9.9 RS79.2 | length 2.4
  Top Layer w0.152: J9.9@197.485,242.57 RS79.2@199.86,242.57
PP7: J10.3 RS131.2 | length 2.4
  Top Layer w0.152: J10.3@217.805,234.95 RS131.2@220.18,234.95
PP8: J6.5 RS107.2 | length 2.4
  Top Layer w0.152: J6.5@136.525,237.49 RS107.2@138.9,237.49
PP9: J7.19 RS20.2 | length 2.4
  Top Layer w0.152: J7.19@156.845,255.27 RS20.2@159.22,255.27
PP10: J8.14 RS63.2 | length 2.4
  Top Layer w0.152: RS63.2@172.25,247.65 J8.14@174.625,247.65
PP11: J8.27 RS6.2 | length 2.4
  Top Layer w0.152: J8.27@177.165,265.43 RS6.2@179.54,265.43
PP12: J9.23 RS16.2 | length 2.4
  Top Layer w0.152: J9.23@197.485,260.35 RS16.2@199.86,260.35
PP13: J10.16 RS53.2 | length 2.4
  Top Layer w0.152: RS53.2@212.89,250.19 J10.16@215.265,250.19
PP14: J11.6 RS117.2 | length 2.4
  Top Layer w0.152: RS117.2@233.21,237.49 J11.6@235.585,237.49
PP15: J11.5 RS118.2 | length 2.4
  Top Layer w0.152: J11.5@238.125,237.49 RS118.2@240.5,237.49
PP16: J5.10 RS73.2 | length 2.4
  Top Layer w0.152: RS73.2@111.29,242.57 J5.10@113.665,242.57
PP17: J6.20 RS17.2 | length 2.4
  Top Layer w0.152: RS17.2@131.61,255.27 J6.20@133.985,255.27
PP18: J7.4 RS123.2 | length 2.4
  Top Layer w0.152: RS123.2@151.93,234.95 J7.4@154.305,234.95
PP19: J7.5 RS113.2 | length 2.4
  Top Layer w0.152: J7.5@156.845,237.49 RS113.2@159.22,237.49
PP20: J8.28 RS5.2 | length 2.4
  Top Layer w0.152: RS5.2@172.25,265.43 J8.28@174.625,265.43
PP21: J9.4 RS129.2 | length 2.4
  Top Layer w0.152: RS129.2@192.57,234.95 J9.4@194.945,234.95
PP22: J9.25 RS12.2 | length 2.4
  Top Layer w0.152: J9.25@197.485,262.89 RS12.2@199.86,262.89
PP23: J10.13 RS68.2 | length 2.4
  Top Layer w0.152: J10.13@217.805,247.65 RS68.2@220.18,247.65
PP24: J11.20 RS27.2 | length 2.4
  Top Layer w0.152: RS27.2@233.21,255.27 J11.20@235.585,255.27
PP25: J12.6 RS119.2 | length 2.4
  Top Layer w0.152: RS119.2@253.53,237.49 J12.6@255.905,237.49
PP26: J12.3 RS135.2 | length 2.4
  Top Layer w0.152: J12.3@258.445,234.95 RS135.2@260.82,234.95
PP27: J5.8 RS89.2 | length 2.4
  Top Layer w0.152: RS89.2@111.29,240.03 J5.8@113.665,240.03
PP28: J6.6 RS112.2 | length 2.4
  Top Layer w0.152: RS112.2@131.61,237.49 J6.6@133.985,237.49
PP29: J6.3 RS122.2 | length 2.4
  Top Layer w0.152: J6.3@136.525,234.95 RS122.2@138.9,234.95
PP30: J7.20 RS19.2 | length 2.4
  Top Layer w0.152: RS19.2@151.93,255.27 J7.20@154.305,255.27
PP31: J8.4 RS124.2 | length 2.4
  Top Layer w0.152: RS124.2@172.25,234.95 J8.4@174.625,234.95
PP32: J8.29 RS2.2 | length 2.4
  Top Layer w0.152: J8.29@177.165,267.97 RS2.2@179.54,267.97
PP33: J9.13 RS65.2 | length 2.4
  Top Layer w0.152: J9.13@197.485,247.65 RS65.2@199.86,247.65
PP34: J10.14 RS67.2 | length 2.4
  Top Layer w0.152: RS67.2@212.89,247.65 J10.14@215.265,247.65
PP35: J11.8 RS101.2 | length 2.4
  Top Layer w0.152: RS101.2@233.21,240.03 J11.8@235.585,240.03
PP36: J11.3 RS133.2 | length 2.4
  Top Layer w0.152: J11.3@238.125,234.95 RS133.2@240.5,234.95
PP37: J12.18 RS43.2 | length 2.4
  Top Layer w0.152: RS43.2@253.53,252.73 J12.18@255.905,252.73
PP38: J12.5 RS120.2 | length 2.4
  Top Layer w0.152: J12.5@258.445,237.49 RS120.2@260.82,237.49
PP39: J9.14 RS66.2 | length 2.4
  Top Layer w0.152: RS66.2@192.57,247.65 J9.14@194.945,247.65
PP40: J5.6 RS105.2 | length 2.4
  Top Layer w0.152: RS105.2@111.29,237.49 J5.6@113.665,237.49
PP41: J6.18 RS31.2 | length 2.4
  Top Layer w0.152: RS31.2@131.61,252.73 J6.18@133.985,252.73
PP42: J7.6 RS108.2 | length 2.4
  Top Layer w0.152: RS108.2@151.93,237.49 J7.6@154.305,237.49
PP43: J7.3 RS128.2 | length 2.4
  Top Layer w0.152: J7.3@156.845,234.95 RS128.2@159.22,234.95
PP44: J8.26 RS9.2 | length 2.4
  Top Layer w0.152: RS9.2@172.25,262.89 J8.26@174.625,262.89
PP45: J9.8 RS98.2 | length 2.4
  Top Layer w0.152: RS98.2@192.57,240.03 J9.8@194.945,240.03
PP46: J9.5 RS111.2 | length 2.4
  Top Layer w0.152: J9.5@197.485,237.49 RS111.2@199.86,237.49
PP47: J10.15 RS54.2 | length 2.4
  Top Layer w0.152: J10.15@217.805,250.19 RS54.2@220.18,250.19
PP48: J11.18 RS41.2 | length 2.4
  Top Layer w0.152: RS41.2@233.21,252.73 J11.18@235.585,252.73
PP49: J12.8 RS103.2 | length 2.4
  Top Layer w0.152: RS103.2@253.53,240.03 J12.8@255.905,240.03
PP50: J12.13 RS72.2 | length 2.4
  Top Layer w0.152: J12.13@258.445,247.65 RS72.2@260.82,247.65
PP51: J5.5 RS106.2 | length 2.4
  Top Layer w0.152: J5.5@116.205,237.49 RS106.2@118.58,237.49
PP52: J6.4 RS127.2 | length 2.4
  Top Layer w0.152: RS127.2@131.61,234.95 J6.4@133.985,234.95
PP53: J6.13 RS60.2 | length 2.4
  Top Layer w0.152: J6.13@136.525,247.65 RS60.2@138.9,247.65
PP54: J7.18 RS33.2 | length 2.4
  Top Layer w0.152: RS33.2@151.93,252.73 J7.18@154.305,252.73
PP55: J8.6 RS109.2 | length 2.4
  Top Layer w0.152: RS109.2@172.25,237.49 J8.6@174.625,237.49
PP56: J8.15 RS50.2 | length 2.4
  Top Layer w0.152: J8.15@177.165,250.19 RS50.2@179.54,250.19
PP57: J9.29 RS4.2 | length 2.4
  Top Layer w0.152: J9.29@197.485,267.97 RS4.2@199.86,267.97
PP58: J10.4 RS130.2 | length 2.4
  Top Layer w0.152: RS130.2@212.89,234.95 J10.4@215.265,234.95
PP59: J11.10 RS85.2 | length 2.4
  Top Layer w0.152: RS85.2@233.21,242.57 J11.10@235.585,242.57
PP60: J11.13 RS70.2 | length 2.4
  Top Layer w0.152: J11.13@238.125,247.65 RS70.2@240.5,247.65
PP61: J12.16 RS57.2 | length 2.4
  Top Layer w0.152: RS57.2@253.53,250.19 J12.16@255.905,250.19
PP62: J12.7 RS104.2 | length 2.4
  Top Layer w0.152: J12.7@258.445,240.03 RS104.2@260.82,240.03
PP63: J5.4 RS121.2 | length 2.4
  Top Layer w0.152: RS121.2@111.29,234.95 J5.4@113.665,234.95
PP64: J6.19 RS18.2 | length 2.4
  Top Layer w0.152: J6.19@136.525,255.27 RS18.2@138.9,255.27
PP65: J7.8 RS92.2 | length 2.4
  Top Layer w0.152: RS92.2@151.93,240.03 J7.8@154.305,240.03
PP66: J7.9 RS81.2 | length 2.4
  Top Layer w0.152: J7.9@156.845,242.57 RS81.2@159.22,242.57
PP67: J8.13 RS64.2 | length 2.4
  Top Layer w0.152: J8.13@177.165,247.65 RS64.2@179.54,247.65
PP68: J9.28 RS7.2 | length 2.4
  Top Layer w0.152: RS7.2@192.57,265.43 J9.28@194.945,265.43
PP69: J9.3 RS126.2 | length 2.4
  Top Layer w0.152: J9.3@197.485,234.95 RS126.2@199.86,234.95
PP70: J10.17 RS40.2 | length 2.4
  Top Layer w0.152: J10.17@217.805,252.73 RS40.2@220.18,252.73
PP71: J11.16 RS55.2 | length 2.4
  Top Layer w0.152: RS55.2@233.21,250.19 J11.16@235.585,250.19
PP72: J12.10 RS87.2 | length 2.4
  Top Layer w0.152: RS87.2@253.53,242.57 J12.10@255.905,242.57
PP73: J12.9 RS88.2 | length 2.4
  Top Layer w0.152: J12.9@258.445,242.57 RS88.2@260.82,242.57
PP74: J5.7 RS90.2 | length 2.4
  Top Layer w0.152: J5.7@116.205,240.03 RS90.2@118.58,240.03
PP75: J6.14 RS59.2 | length 2.4
  Top Layer w0.152: RS59.2@131.61,247.65 J6.14@133.985,247.65
PP76: J6.7 RS91.2 | length 2.4
  Top Layer w0.152: J6.7@136.525,240.03 RS91.2@138.9,240.03
PP77: J7.17 RS34.2 | length 2.4
  Top Layer w0.152: J7.17@156.845,252.73 RS34.2@159.22,252.73
PP78: J8.8 RS93.2 | length 2.4
  Top Layer w0.152: RS93.2@172.25,240.03 J8.8@174.625,240.03
PP79: J8.5 RS110.2 | length 2.4
  Top Layer w0.152: J8.5@177.165,237.49 RS110.2@179.54,237.49
PP80: J9.18 RS38.2 | length 2.4
  Top Layer w0.152: RS38.2@192.57,252.73 J9.18@194.945,252.73
PP81: J10.6 RS115.2 | length 2.4
  Top Layer w0.152: RS115.2@212.89,237.49 J10.6@215.265,237.49
PP82: J10.9 RS84.2 | length 2.4
  Top Layer w0.152: J10.9@217.805,242.57 RS84.2@220.18,242.57
PP83: J11.15 RS56.2 | length 2.4
  Top Layer w0.152: J11.15@238.125,250.19 RS56.2@240.5,250.19
PP84: J12.14 RS71.2 | length 2.4
  Top Layer w0.152: RS71.2@253.53,247.65 J12.14@255.905,247.65
PP85: J12.15 RS58.2 | length 2.4
  Top Layer w0.152: J12.15@258.445,250.19 RS58.2@260.82,250.19
PP86: J5.9 RS74.2 | length 2.4
  Top Layer w0.152: J5.9@116.205,242.57 RS74.2@118.58,242.57
PP87: J6.17 RS32.2 | length 2.4
  Top Layer w0.152: J6.17@136.525,252.73 RS32.2@138.9,252.73
PP88: J7.14 RS61.2 | length 2.4
  Top Layer w0.152: RS61.2@151.93,247.65 J7.14@154.305,247.65
PP89: J8.10 RS77.2 | length 2.4
  Top Layer w0.152: RS77.2@172.25,242.57 J8.10@174.625,242.57
PP90: J8.9 RS78.2 | length 2.4
  Top Layer w0.152: J8.9@177.165,242.57 RS78.2@179.54,242.57
PP91: J8.25 RS10.2 | length 2.4
  Top Layer w0.152: J8.25@177.165,262.89 RS10.2@179.54,262.89
PP92: J9.27 RS8.2 | length 2.4
  Top Layer w0.152: J9.27@197.485,265.43 RS8.2@199.86,265.43
PP93: J10.19 RS26.2 | length 2.4
  Top Layer w0.152: J10.19@217.805,255.27 RS26.2@220.18,255.27
PP94: J11.14 RS69.2 | length 2.4
  Top Layer w0.152: RS69.2@233.21,247.65 J11.14@235.585,247.65
PP95: J11.9 RS86.2 | length 2.4
  Top Layer w0.152: J11.9@238.125,242.57 RS86.2@240.5,242.57
PP96: J12.17 RS44.2 | length 2.4
  Top Layer w0.152: J12.17@258.445,252.73 RS44.2@260.82,252.73
PP97: J6.10 RS80.2 | length 2.4
  Top Layer w0.152: RS80.2@131.61,242.57 J6.10@133.985,242.57
PP98: J6.16 RS45.2 | length 2.4
  Top Layer w0.152: RS45.2@131.61,250.19 J6.16@133.985,250.19
PP99: J6.9 RS75.2 | length 2.4
  Top Layer w0.152: J6.9@136.525,242.57 RS75.2@138.9,242.57
PP100: J7.15 RS48.2 | length 2.4
  Top Layer w0.152: J7.15@156.845,250.19 RS48.2@159.22,250.19
PP101: J8.20 RS21.2 | length 2.4
  Top Layer w0.152: RS21.2@172.25,255.27 J8.20@174.625,255.27
PP102: J8.7 RS94.2 | length 2.4
  Top Layer w0.152: J8.7@177.165,240.03 RS94.2@179.54,240.03
PP103: J9.10 RS82.2 | length 2.4
  Top Layer w0.152: RS82.2@192.57,242.57 J9.10@194.945,242.57
PP104: J10.8 RS99.2 | length 2.4
  Top Layer w0.152: RS99.2@212.89,240.03 J10.8@215.265,240.03
PP105: J10.7 RS100.2 | length 2.4
  Top Layer w0.152: J10.7@217.805,240.03 RS100.2@220.18,240.03
PP106: J11.17 RS42.2 | length 2.4
  Top Layer w0.152: J11.17@238.125,252.73 RS42.2@240.5,252.73
PP107: J12.4 RS134.2 | length 2.4
  Top Layer w0.152: RS134.2@253.53,234.95 J12.4@255.905,234.95
PP108: J12.19 RS30.2 | length 2.4
  Top Layer w0.152: J12.19@258.445,255.27 RS30.2@260.82,255.27
PP109: J6.8 RS96.2 | length 2.4
  Top Layer w0.152: RS96.2@131.61,240.03 J6.8@133.985,240.03
PP110: J6.15 RS46.2 | length 2.4
  Top Layer w0.152: J6.15@136.525,250.19 RS46.2@138.9,250.19
PP111: J7.16 RS47.2 | length 2.4
  Top Layer w0.152: RS47.2@151.93,250.19 J7.16@154.305,250.19
PP112: J8.24 RS13.2 | length 2.4
  Top Layer w0.152: RS13.2@172.25,260.35 J8.24@174.625,260.35
PP113: J8.19 RS22.2 | length 2.4
  Top Layer w0.152: J8.19@177.165,255.27 RS22.2@179.54,255.27
PP114: J9.16 RS52.2 | length 2.4
  Top Layer w0.152: RS52.2@192.57,250.19 J9.16@194.945,250.19
PP115: J9.7 RS95.2 | length 2.4
  Top Layer w0.152: J9.7@197.485,240.03 RS95.2@199.86,240.03
PP116: J10.20 RS25.2 | length 2.4
  Top Layer w0.152: RS25.2@212.89,255.27 J10.20@215.265,255.27
PP117: J11.4 RS132.2 | length 2.4
  Top Layer w0.152: RS132.2@233.21,234.95 J11.4@235.585,234.95
PP118: J11.7 RS102.2 | length 2.4
  Top Layer w0.152: J11.7@238.125,240.03 RS102.2@240.5,240.03
PP119: J12.20 RS29.2 | length 2.4
  Top Layer w0.152: RS29.2@253.53,255.27 J12.20@255.905,255.27
PP120: J9.30 RS3.2 | length 2.4
  Top Layer w0.152: RS3.2@192.57,267.97 J9.30@194.945,267.97
PP121: J7.10 RS76.2 | length 2.4
  Top Layer w0.152: RS76.2@151.93,242.57 J7.10@154.305,242.57
PP122: J7.13 RS62.2 | length 2.4
  Top Layer w0.152: J7.13@156.845,247.65 RS62.2@159.22,247.65
PP123: J8.18 RS35.2 | length 2.4
  Top Layer w0.152: RS35.2@172.25,252.73 J8.18@174.625,252.73
PP124: J8.23 RS14.2 | length 2.4
  Top Layer w0.152: J8.23@177.165,260.35 RS14.2@179.54,260.35
PP125: J9.24 RS15.2 | length 2.4
  Top Layer w0.152: RS15.2@192.57,260.35 J9.24@194.945,260.35
PP126: J10.10 RS83.2 | length 2.4
  Top Layer w0.152: RS83.2@212.89,242.57 J10.10@215.265,242.57
PP127: J10.5 RS116.2 | length 2.4
  Top Layer w0.152: J10.5@217.805,237.49 RS116.2@220.18,237.49
PP128: J11.19 RS28.2 | length 2.4
  Top Layer w0.152: J11.19@238.125,255.27 RS28.2@240.5,255.27
PP129: J8.16 RS49.2 | length 2.4
  Top Layer w0.152: RS49.2@172.25,250.19 J8.16@174.625,250.19
PP130: J8.17 RS36.2 | length 2.4
  Top Layer w0.152: J8.17@177.165,252.73 RS36.2@179.54,252.73
PP131: J9.20 RS24.2 | length 2.4
  Top Layer w0.152: RS24.2@192.57,255.27 J9.20@194.945,255.27
PP132: J9.17 RS37.2 | length 2.4
  Top Layer w0.152: J9.17@197.485,252.73 RS37.2@199.86,252.73
PP133: J10.18 RS39.2 | length 2.4
  Top Layer w0.152: RS39.2@212.89,252.73 J10.18@215.265,252.73
PP134: J9.26 RS11.2 | length 2.4
  Top Layer w0.152: RS11.2@192.57,262.89 J9.26@194.945,262.89
PP135: J9.19 RS23.2 | length 2.4
  Top Layer w0.152: J9.19@197.485,255.27 RS23.2@199.86,255.27
SCL3: IC1.6 J4.8 R2.1 | length 273.2
  Top Layer w0.152: IC1.6@195.31,130.045 195.768,130.045 196.85,131.127 250.507,131.127 273.685,154.305 273.685,328.93 J4.8@276.225,331.47 277.495,330.2 280.505,330.2 R2.1@281.775,331.47
SCL4: J3.1 J4.4 R4.1 | length 23.5
  Top Layer w0.152: J4.4@276.225,326.39 277.495,327.66 280.505,327.66 R4.1@281.775,326.39
  L2 w0.152: J3.1@262.255,330.835 262.255,328.93 264.795,326.39 J4.4@276.225,326.39
SDA3: IC1.1 J4.9 R1.1 | length 273.9
  Top Layer w0.152: IC1.1@195.31,132.845 195.768,132.845 196.85,131.762 250.19,131.762 273.05,154.623 273.05,330.835 274.955,332.74 277.495,332.74 J4.9@278.765,334.01 R1.1@281.775,334.01
SDA4: J3.4 J4.5 R3.1 | length 12.7
  Top Layer w0.152: J4.5@278.765,328.93 R3.1@281.775,328.93
  L2 w0.152: J3.4@269.875,330.835 270.51,330.2 277.495,330.2 J4.5@278.765,328.93
VSS: C10.1 IC1.2 IC1.7 NT1.2 | length 276
  Top Layer w0.152: C10.1@191.77,132.245 191.77,133.032 192.405,133.667 193.992,133.667 194.31,133.35 ; IC1.2@194.31,132.845 194.31,133.35 ; NT1.2@275.59,335.915 272.415,332.74 272.415,154.94 249.873,132.398 197.485,132.398 196.215,133.667 194.627,133.667 194.31,133.35
  Top Layer w0.305: IC1.7@194.31,131.445 IC1.2@194.31,132.845
pads on no net: FTG1.FTG2 FTG2.FTG2 FTG3.FTG2 IC1.3 IC1.4 J5.17 J5.18 J5.19 J5.20

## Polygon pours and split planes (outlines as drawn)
GND on Top Layer "GND_L01_P002" (solid, remove dead copper, pour order 2): 76.69,339.725 295.42,339.725 295.42,110.995 251.137,110.995 217.137,76.995 154.973,76.995 120.972,110.995 76.69,110.995
GND on Bottom Layer "GND_L08_P016" (solid, remove dead copper, pour order 16): 76.69,339.725 295.42,339.725 295.42,110.995 251.137,110.995 217.137,76.995 154.973,76.995 120.972,110.995 76.69,110.995
GND on L2 "GND_L02_P004" (solid, remove dead copper, pour order 4): 76.69,339.725 295.42,339.725 295.42,110.995 251.137,110.995 217.137,76.995 154.973,76.995 120.972,110.995 76.69,110.995
GND on L3 "GND_L03_P006" (solid, remove dead copper, pour order 6): 76.69,339.725 295.42,339.725 295.42,110.995 251.137,110.995 217.137,76.995 154.973,76.995 120.972,110.995 76.69,110.995
GND on L4 "GND_L04_P008" (solid, remove dead copper, pour order 8): 76.69,339.725 295.42,339.725 295.42,110.995 251.137,110.995 217.137,76.995 154.973,76.995 120.972,110.995 76.69,110.995
GND on L5 "GND_L05_P010" (solid, remove dead copper, pour order 10): 76.69,339.725 295.42,339.725 295.42,110.995 251.137,110.995 217.137,76.995 154.973,76.995 120.972,110.995 76.69,110.995
GND on L6 "GND_L06_P012" (solid, remove dead copper, pour order 12): 76.69,339.725 295.42,339.725 295.42,110.995 251.137,110.995 217.137,76.995 154.973,76.995 120.972,110.995 76.69,110.995
GND on L7 "GND_L07_P014" (solid, remove dead copper, pour order 14): 76.69,339.725 295.42,339.725 295.42,110.995 251.137,110.995 217.137,76.995 154.973,76.995 120.972,110.995 76.69,110.995

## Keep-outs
Keep-Out Layer:
  lines w0.2: 76.055,110.36 76.055,335.36 cw(c81.055,335.36) 81.055,340.36 291.055,340.36 cw(c291.055,335.36) 296.055,335.36 296.055,110.36 252.449,110.36 ccw(c252.449,107.96) 250.752,109.657 217.455,76.36 154.655,76.36 121.358,109.657 ccw(c119.661,107.96) 119.661,110.36 76.055,110.36
  lines w1: 93.555,110.36 98.555,110.36 ; 136.039,94.976 139.574,91.441 ; 232.544,91.449 236.08,94.985 ; 273.555,110.36 278.555,110.36
Multi-Layer:
  lines w0.2: 76.055,317.5 114.3,317.5 116.84,320.04 116.84,340.36

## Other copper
Top Layer:
  text "TOP" at 287.02,297.18 h1.5 r90
  text "EDA-03517-V2" at 287.02,279.4 h1.5 r90
  text ".Layer_Name" at 144.145,41.91 h1.91 r45
  text "1" at 143.192,36.83 h2.54
L2:
  text ".Layer_Name" at 149.225,41.91 h1.91 r45
  text "2" at 147.955,36.83 h2.54
L3:
  text ".Layer_Name" at 156.21,43.815 h1.91 r45
  text "3" at 152.718,36.83 h2.54
L4:
  text ".Layer_Name" at 159.385,41.91 h1.91 r45
  text "4" at 157.797,36.83 h2.54
L5:
  text ".Layer_Name" at 166.37,43.815 h1.91 r45
  text "5" at 162.877,36.83 h2.54
L6:
  text ".Layer_Name" at 169.545,41.91 h1.91 r45
  text "6" at 168.275,36.83 h2.54
L7:
  text ".Layer_Name" at 175.895,43.18 h1.91 r45
  text "7" at 173.037,36.83 h2.54
Bottom Layer:
  text "BOT" at 285.433,297.18 h1.5 r270
  text "EDA-03517-V2" at 285.433,279.4 h1.5 r270
  text ".Layer_Name" at 191.77,53.975 h1.91 r45
  text "8" at 178.118,36.83 h2.54

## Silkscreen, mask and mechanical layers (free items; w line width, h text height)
Top Overlay:
  region: 108.605,326.505 109.105,327.755 109.855,327.005
  lines w0.2: 118.745,227.965 119.38,228.6 119.38,236.22 ; 130.81,233.68 130.81,228.6 131.445,227.965 ; 130.81,256.54 130.81,260.985 ; 139.065,227.965 139.7,228.6 139.7,233.68 ; 139.065,260.985 139.7,260.35 139.7,256.54 ; 151.13,233.68 151.13,228.6 151.765,227.965 ; 151.13,256.54 151.13,260.35 151.765,260.985 ; 159.385,227.965 160.02,228.6 160.02,233.68 ; 159.385,260.985 160.02,260.35 160.02,256.54 ; 163.195,256.54 163.195,260.985 ; 167.64,269.24 167.64,273.685 ; 171.45,233.68 171.45,228.6 172.085,227.965 ; 171.45,269.24 171.45,273.05 172.085,273.685 ; 179.705,227.965 180.34,228.6 180.34,233.68 ; 179.705,273.685 180.34,273.05 180.34,269.24 ; 191.77,233.68 191.77,228.6 192.405,227.965 ; 191.77,269.24 191.77,273.05 192.405,273.685 ; 200.025,227.965 200.66,228.6 200.66,233.68 ; 200.025,273.685 200.66,273.05 200.66,269.24 ; 208.28,256.54 208.28,273.685 ; 212.09,233.68 212.09,228.6 212.725,227.965 ; 212.09,256.54 212.09,260.35 212.725,260.985 ; 220.345,227.965 220.98,228.6 220.98,233.68 ; 220.345,260.985 220.98,260.35 220.98,256.54 ; 232.41,233.68 232.41,228.6 233.045,227.965 ; 232.41,256.54 232.41,260.35 233.045,260.985 ; 240.665,227.965 241.3,228.6 241.3,233.68 ; 240.665,260.985 241.3,260.35 241.3,256.54 ; 252.73,233.68 252.73,228.6 253.365,227.965 ; 252.73,256.54 252.73,260.35 253.365,260.985 ; 260.985,227.965 261.62,228.6 261.62,233.68 ; 260.985,260.985 261.62,260.35 261.62,256.54
  lines w0.35: 109.105,327.005 111.105,329.005 108.605,329.005 110.355,330.755 ; 105.855,325.755 109.855,333.755 113.855,325.755 105.855,325.755
  lines w0.5: 78.74,317.5 114.3,317.5 116.84,320.04 116.84,337.82
  text "HV" at 86.36,334.645 h1.5
  text "HV" at 100.33,334.645 h1.5
  text "Licensed under CERN OHL v.1.2" at 173.355,329.565 h1.14
  text "http://ohwr.org/cernohl" at 177.165,327.025 h1.14
  text "HIGH" at 107.791,323.215 h1.5
  text "SCL" at 262.89,322.58 h1 r90
  text "+3.3V" at 265.43,322.58 h1 r90
  text "GND" at 267.97,322.58 h1 r90
  text "SDA" at 270.51,322.58 h1 r90
  text "VOLTAGE" at 105.41,320.675 h1.5
  text "HGC Sensor 136 Channels 6 inch - Probe Card" at 152.4,317.5 h2
  text "http://ohwr.org/projects/array" at 173.355,314.325 h1.27
  text "EDA-03517-V2" at 177.8,305.435 h1.5
  text "TOP" at 184.15,302.895 h1.5
  text ".Layer_Name" at 200.66,50.8 h1.91
Bottom Overlay:
  region: 111.105,326.505 110.605,327.755 109.855,327.005
  lines w0.35: 109.355,330.755 111.105,329.005 108.605,329.005 110.605,327.005 ; 105.855,325.755 109.855,333.755 113.855,325.755 105.855,325.755
  lines w0.5: 78.74,317.5 114.3,317.5 116.84,320.04 116.84,337.82
  text "HIGH" at 111.919,323.215 h1.5
  text "VOLTAGE" at 114.3,320.675 h1.5
  text "EDA-03517-V2" at 193.675,305.435 h1.5
  text "BOT" at 187.96,302.895 h1.5
  text ".Layer_Name" at 241.3,50.8 h1.91
Top Paste:
  text ".Layer_Name" at 200.66,45.72 h1.91
Bottom Paste:
  text ".Layer_Name" at 241.3,45.72 h1.91
Top Solder:
  lines w0.8: 93.055,110.36 99.055,110.36 ; 135.685,95.33 139.928,91.087 ; 232.191,91.096 236.434,95.339 ; 273.055,110.36 279.055,110.36
  text ".Layer_Name" at 200.66,48.26 h1.91
Bottom Solder:
  lines w0.8: 93.055,110.36 99.055,110.36 ; 135.685,95.33 139.928,91.087 ; 232.191,91.096 236.434,95.339 ; 273.055,110.36 279.055,110.36
  text ".Layer_Name" at 241.3,48.26 h1.91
